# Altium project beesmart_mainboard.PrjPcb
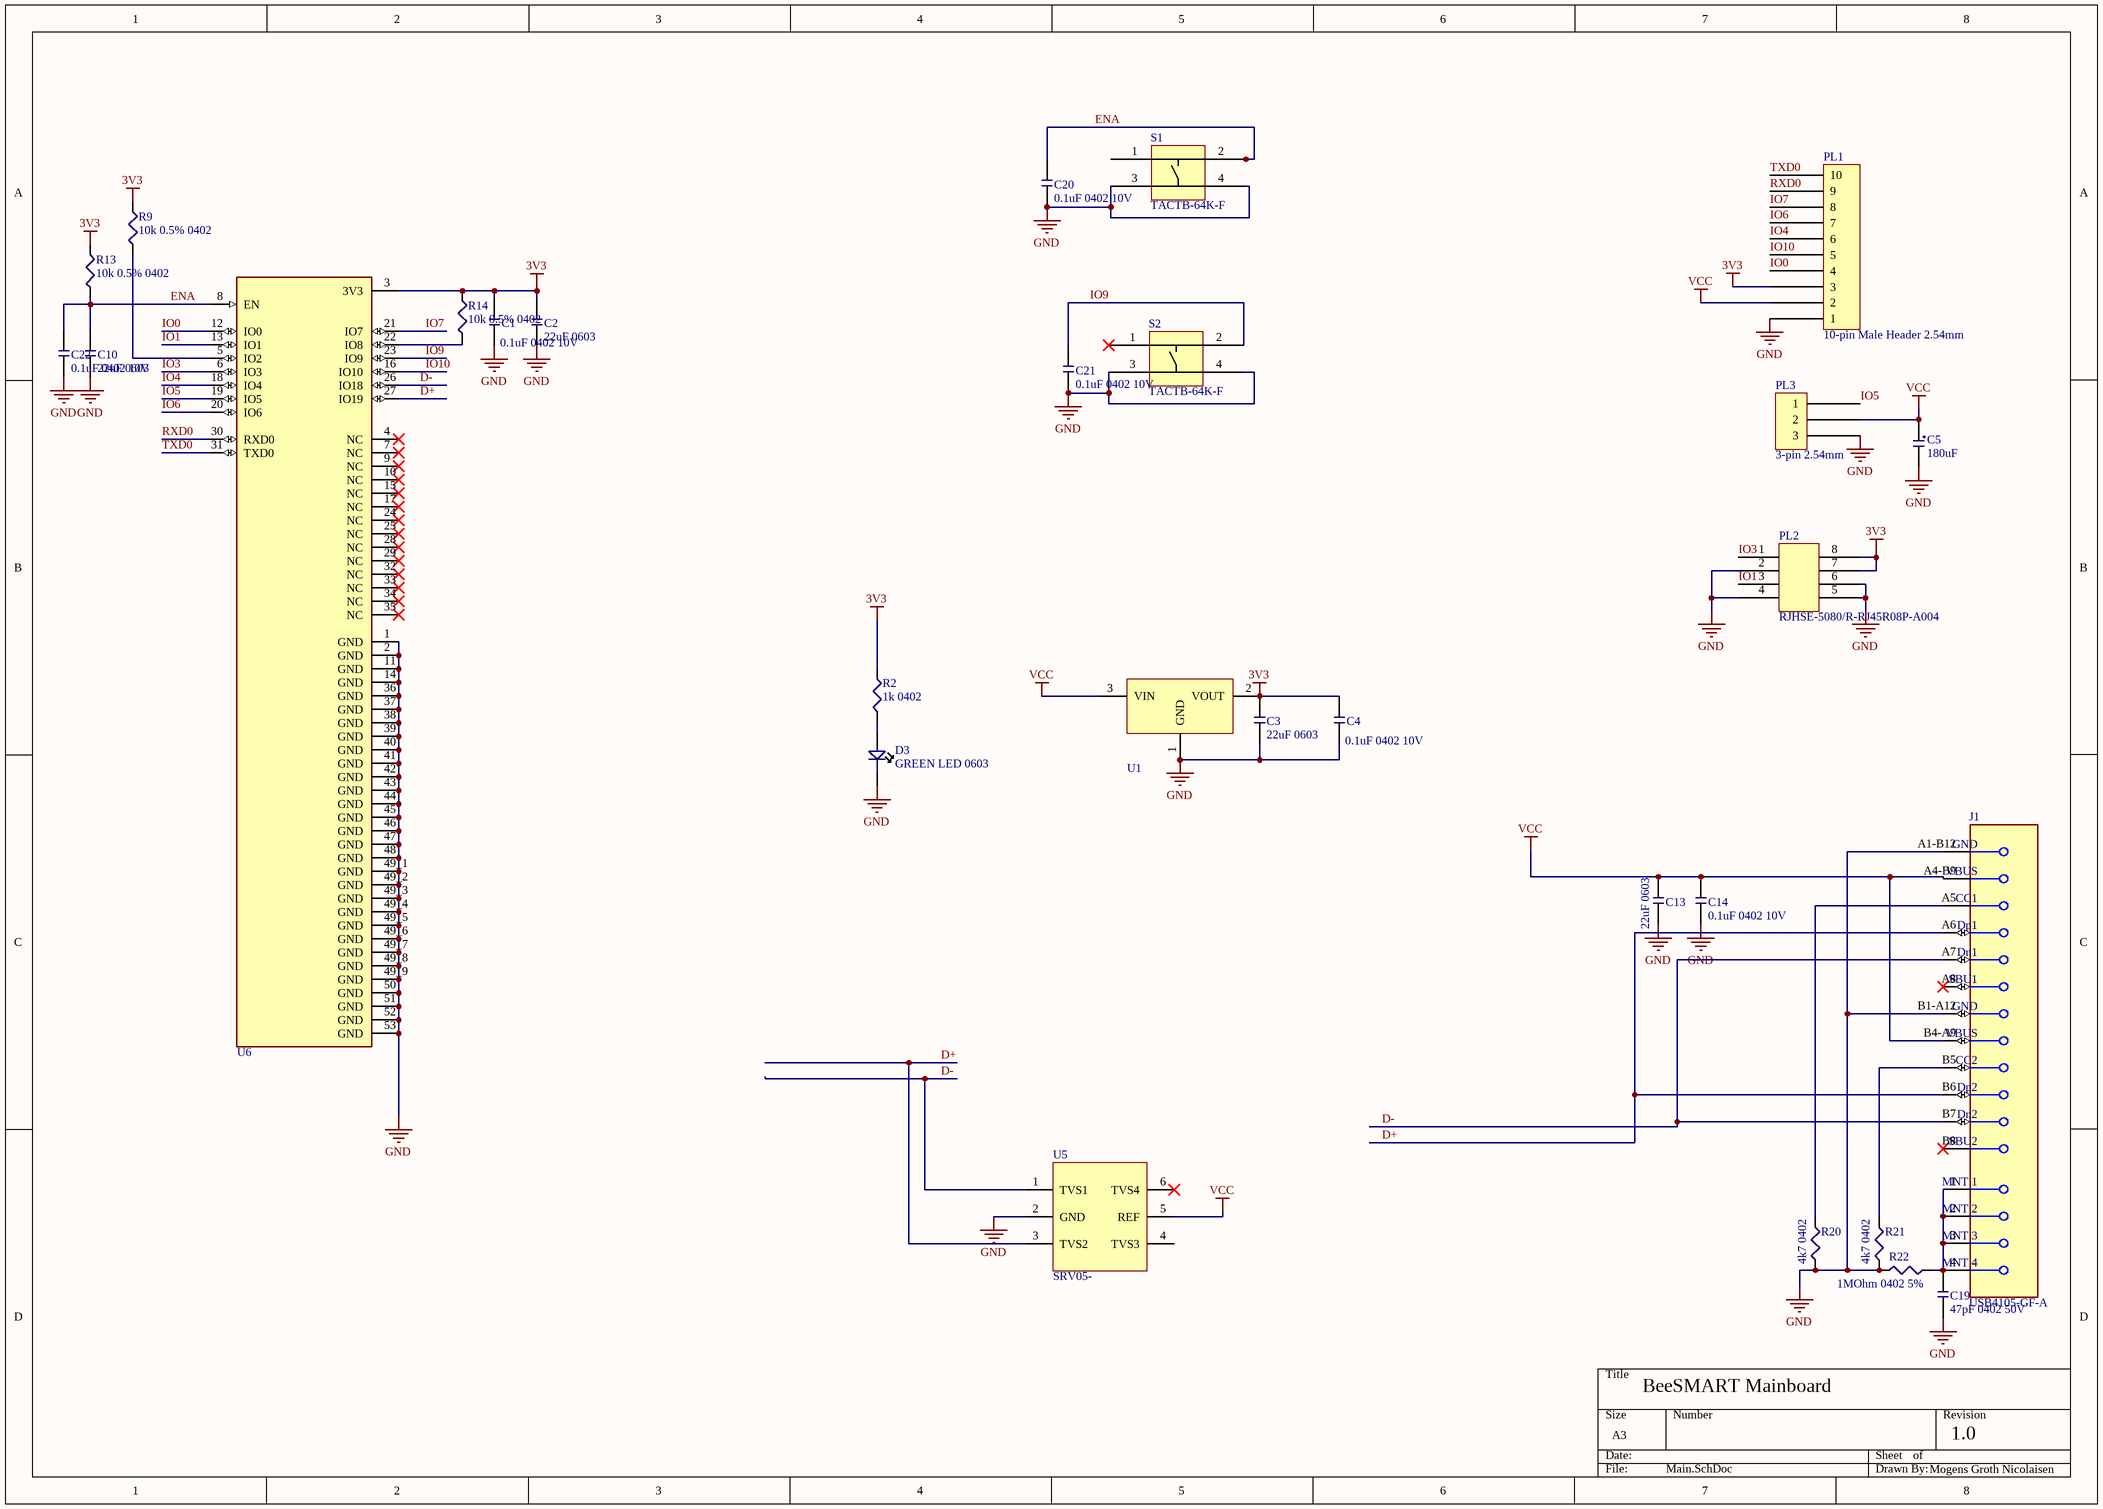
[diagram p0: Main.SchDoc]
GlobalCompanyName: na; GlobalDrawnBy: Mogens Groth Nicolaisen; GlobalProjectName: BeeSMART Mainboard; GlobalProjectRevision: 1.0
1 sheet, 29 parts. Net scope: hierarchical (ports join the sheet entries above them; power ports are global).
Board file: beesmart_mainboard.PcbDoc

## Sheet Main.SchDoc: Main
size A3; DrawnBy: Mogens Groth Nicolaisen; DocumentNumber: 2; Revision: 1.0; SheetNumber: 2; SheetTotal: 7

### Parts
C1  0.1uF 0402 10V  [CAP_0402]
C2  22uF 0603  [CAP_0603]
C3  22uF 0603  [CAP_0603]
C4  0.1uF 0402 10V  [CAP_0402]
C5  180uF  [Capacitor 8x22]
C10  22uF 0603  [CAP_0603]
C13  22uF 0603  [CAP_0603]
C14  0.1uF 0402 10V  [CAP_0402]
C19  47pF 0402 50V  [CAP_0402]
C20  0.1uF 0402 10V  [CAP_0402]
C21  0.1uF 0402 10V  [CAP_0402]
C22  0.1uF 0402 10V  [CAP_0402]
D3  GREEN LED 0603  [0603 LED]
J1  USB4105-GF-A  [FP-USB4105-GF-A-MFG]
PL1  10-pin Male Header 2.54mm  [10-pin 2.54mm header]
PL2  RJHSE-5080/R-RJ45R08P-A004  [AMPHENOL RJHSE-5080]
PL3  3-pin 2.54mm  [3-pin 2.54mm header]
R2  1k 0402  [RES_0402]
R9  10k 0.5% 0402  [RES_0402]
R13  10k 0.5% 0402  [RES_0402]
R14  10k 0.5% 0402  [RES_0402]
R20  4k7 0402  [RES_0402]
R21  4k7 0402  [RES_0402]
R22  1MOhm 0402 5%  [RES_0402]
S1  TACTB-64K-F  [TACTB-64K-F]
S2  TACTB-64K-F  [TACTB-64K-F]
U1  3.3V LDO 1A  [SOT230P700X180-4N]  (value not drawn)
U5  SRV05-  [SOT95P280X145-6N]
U6  ESP32-C3-MINI-1-N4  [ESP32-C3-MINI-1-N4-Footprint-1]  (value not drawn)

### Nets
3V3: C1.2 C2.2 C3.2 C4.2 PL1.3 PL2.7 PL2.8 R2.2 R9.2 R13.2 R14.2 U1.2(VOUT) U6.3(3V3)
GND: C1.1 C2.1 C3.1 C4.1 C5.2 C10.1 C13.1 C14.1 C19.1 C20.1 C21.1 C22.2 D3.2 J1.A1-B12(GND) J1.B1-A12(GND) PL1.1 PL2.2 PL2.4 PL2.5 PL2.6 PL3.3 R20.1 R21.1 R22.1 S1.3 S1.4 S2.3 S2.4 U1.1(GND) U5.2(GND) U6.1(GND) U6.2(GND) U6.11(GND) U6.14(GND) U6.36(GND) U6.37(GND) U6.38(GND) U6.39(GND) U6.40(GND) U6.41(GND) U6.42(GND) U6.43(GND) U6.44(GND) U6.45(GND) U6.46(GND) U6.47(GND) U6.48(GND) U6.49_1(GND) U6.49_2(GND) U6.49_3(GND) U6.49_4(GND) U6.49_5(GND) U6.49_6(GND) U6.49_7(GND) U6.49_8(GND) U6.49_9(GND) U6.50(GND) U6.51(GND) U6.52(GND) U6.53(GND)
VCC: C5.1 C13.2 C14.2 J1.A4-B9(VBUS) J1.B4-A9(VBUS) PL1.2 PL3.2 U1.3(VIN) U5.5(REF)
D+: J1.A6(Dp1) J1.B6(Dp2) U5.3(TVS2) U6.27(IO19)
D-: J1.A7(Dn1) J1.B7(Dn2) U5.1(TVS1) U6.26(IO18)
ENA: C10.2 C20.2 C22.1 R13.1 S1.2 U6.8(EN)
IO0: PL1.4 U6.12(IO0)
IO1: PL2.3 U6.13(IO1)
IO3: PL2.1 U6.6(IO3)
IO4: PL1.6 U6.18(IO4)
IO5: PL3.1 U6.19(IO5)
IO6: PL1.7 U6.20(IO6)
IO7: PL1.8 U6.21(IO7)
IO9: C21.2 S2.2 U6.23(IO9)
IO10: PL1.5 U6.16(IO10)
RXD0: PL1.9 U6.30(RXD0)
TXD0: PL1.10 U6.31(TXD0)
NetC19_2: C19.2 J1.1(MNT_1) J1.2(MNT_2) J1.3(MNT_3) J1.4(MNT_4) R22.2
NetD3_1: D3.1 R2.1
NetJ1_A5: J1.A5(CC1) R20.2
NetJ1_B5: J1.B5(CC2) R21.2
NetR9_1: R9.1 U6.5(IO2)
NetR14_1: R14.1 U6.22(IO8)

Not connected (* = marked no-connect by the designer): J1 A8(SBU1)* B8(SBU2)*; S1 1; S2 1*; U5 4(TVS3) 6(TVS4)*; U6 4(NC)* 7(NC)* 9(NC)* 10(NC)* 15(NC)* 17(NC)* 24(NC)* 25(NC)* 28(NC)* 29(NC)* 32(NC)* 33(NC)* 34(NC)* 35(NC)*

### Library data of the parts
C1 C4 C14 C20-C22 = CMP-00101-1: 0.1uF 0402 10V X7R 10%; Value: 100 nF
C2 C3 C10 C13 = CMP-00148-1: Cap Ceramic 22uF 6.3V X5R 20% SMD 0603 85C Cardboard T/R
C5 = CMP-002-0002-4: CAP ALUM 180UF 20% 50V RADIAL; Mfg. Part Number: EEU-FR1H181LB
C19 = CMP-00099-1: 47pF 0402 50V X7R 5%; Tolerance: 10%
D3 = CMP-008-0000-1: SMD GREEN WATER CLEAR; Mfg. Part Number: APT1608SGC
J1 = CMP-003-0034-0.0: Conn USB 2.0 Type C RCP 24 POS 0.3mm/0.5mm Solder RA SMD 24 Terminal 1 Port T/R; Gender: Receptacle; Mating Cycles: 10000; Number of Ports: 1; Shielding: Shielded
PL1 = CMP-003-0020-0.0: 10 Positions Header Connector 0.100" (2.54mm) Through Hole Gold
PL2 = CMP-003-0022-0.1: CONN MOD JACK 8P8C R/A UNSHLD; Shielding: Unshielded; Gender: Female; Current Rating: 1.5A; Voltage Rating: 125V; Contact Resistance: 20mR; Connector Type: Jack, RJ45; Number of Ports: 1; Direction: Up; Number of Contacts: 8; Pitch: 2.03mm
PL3 = CMP-003-0018-1: Pin header 3-pin 2.54mm male; Mfg. Part Number: DS1021-1*3SF1-1; DynamicData: Ningbo Connfly Electric DS1021-1*3SF1-1; Cat: Connectors; LatestRevision: 1
R2 = CMP-001-0025-3: RES SMD 1K OHM 1% 1/16W 0402; Mfg. Part Number: CRG0402F1K0
R9 R13 R14 = CMP-0001-00029-2: RES 10K OHM 0.5% 1/16W 0402; Manufacturer Part No.: RC0402DR-0710KL
R20 R21 = CMP-001-0029-3: RES SMD 4.7K OHM 1% 1/16W 0402; Mfg. Part Number: RC1005F472CS; Tolerance: 1
R22 = CMP-001-0065-1: RES SMD 1M OHM 5% 1/16W 0402; Mfg. Part Number: CR0402JC1MS001; Value: 1Mega
S1 S2 = CMP-013-0002-1: Microswitch TACT; SPST-NO; Positions:2; 0.05A/12VDC;
U1 = CMP-00114-2: IC REG LINEAR 3.3V 1A SOT223; Dropout Voltage: 1.1V; Number of Regulators: 1; Max Input Voltage: 13V; Operating Supply Current: 3.5mA; Power Supply Rejection Ratio (PSRR): 70dB; Polarity: Positive; Accuracy: 1%; Reference Voltage: 1.262V; Output Type: Fixed
U5 = CMP-016-0020-1: SRV05 Series 4 Ch 3.5 pF 15 Vclamp Steering Diode/TVS Array Combo - SOT-23-6; Capacitance: 3.5pF; Clamping Voltage: 15V; Direction: Unidirectional; Leakage Current: 5uA; Number of Channels: 4; Number of Elements: 1; Peak Pulse Current: 5A; Peak Pulse Power: 500W; Reverse Breakdown Voltage: 6V; Reverse Standoff Voltage: 5V; Test Current: 1mA
U6 = CMP-00162-1: Bluetooth, WiFi 802.11b/g/n, Bluetooth v5.0 Transceiver Module 2.412GHz ~ 2.484GHz PCB Trace Surface Mount

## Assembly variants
Default: not fitted J1 PL2 PL2 PL3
